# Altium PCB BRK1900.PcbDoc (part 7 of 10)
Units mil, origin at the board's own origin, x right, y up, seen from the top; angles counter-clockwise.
Board outline 8858.27 x 5905.51 mil, 10 copper layers (L1-TOP, L2-GND, L3-SIG1, L4-GND, L5-PWR, L6-PWR, L7-GND, L8-SIG2, L9-GND, L10-BOT), stack 48.824 mil thick; 507 components, 607 nets, 2498 pads, 2210 vias.
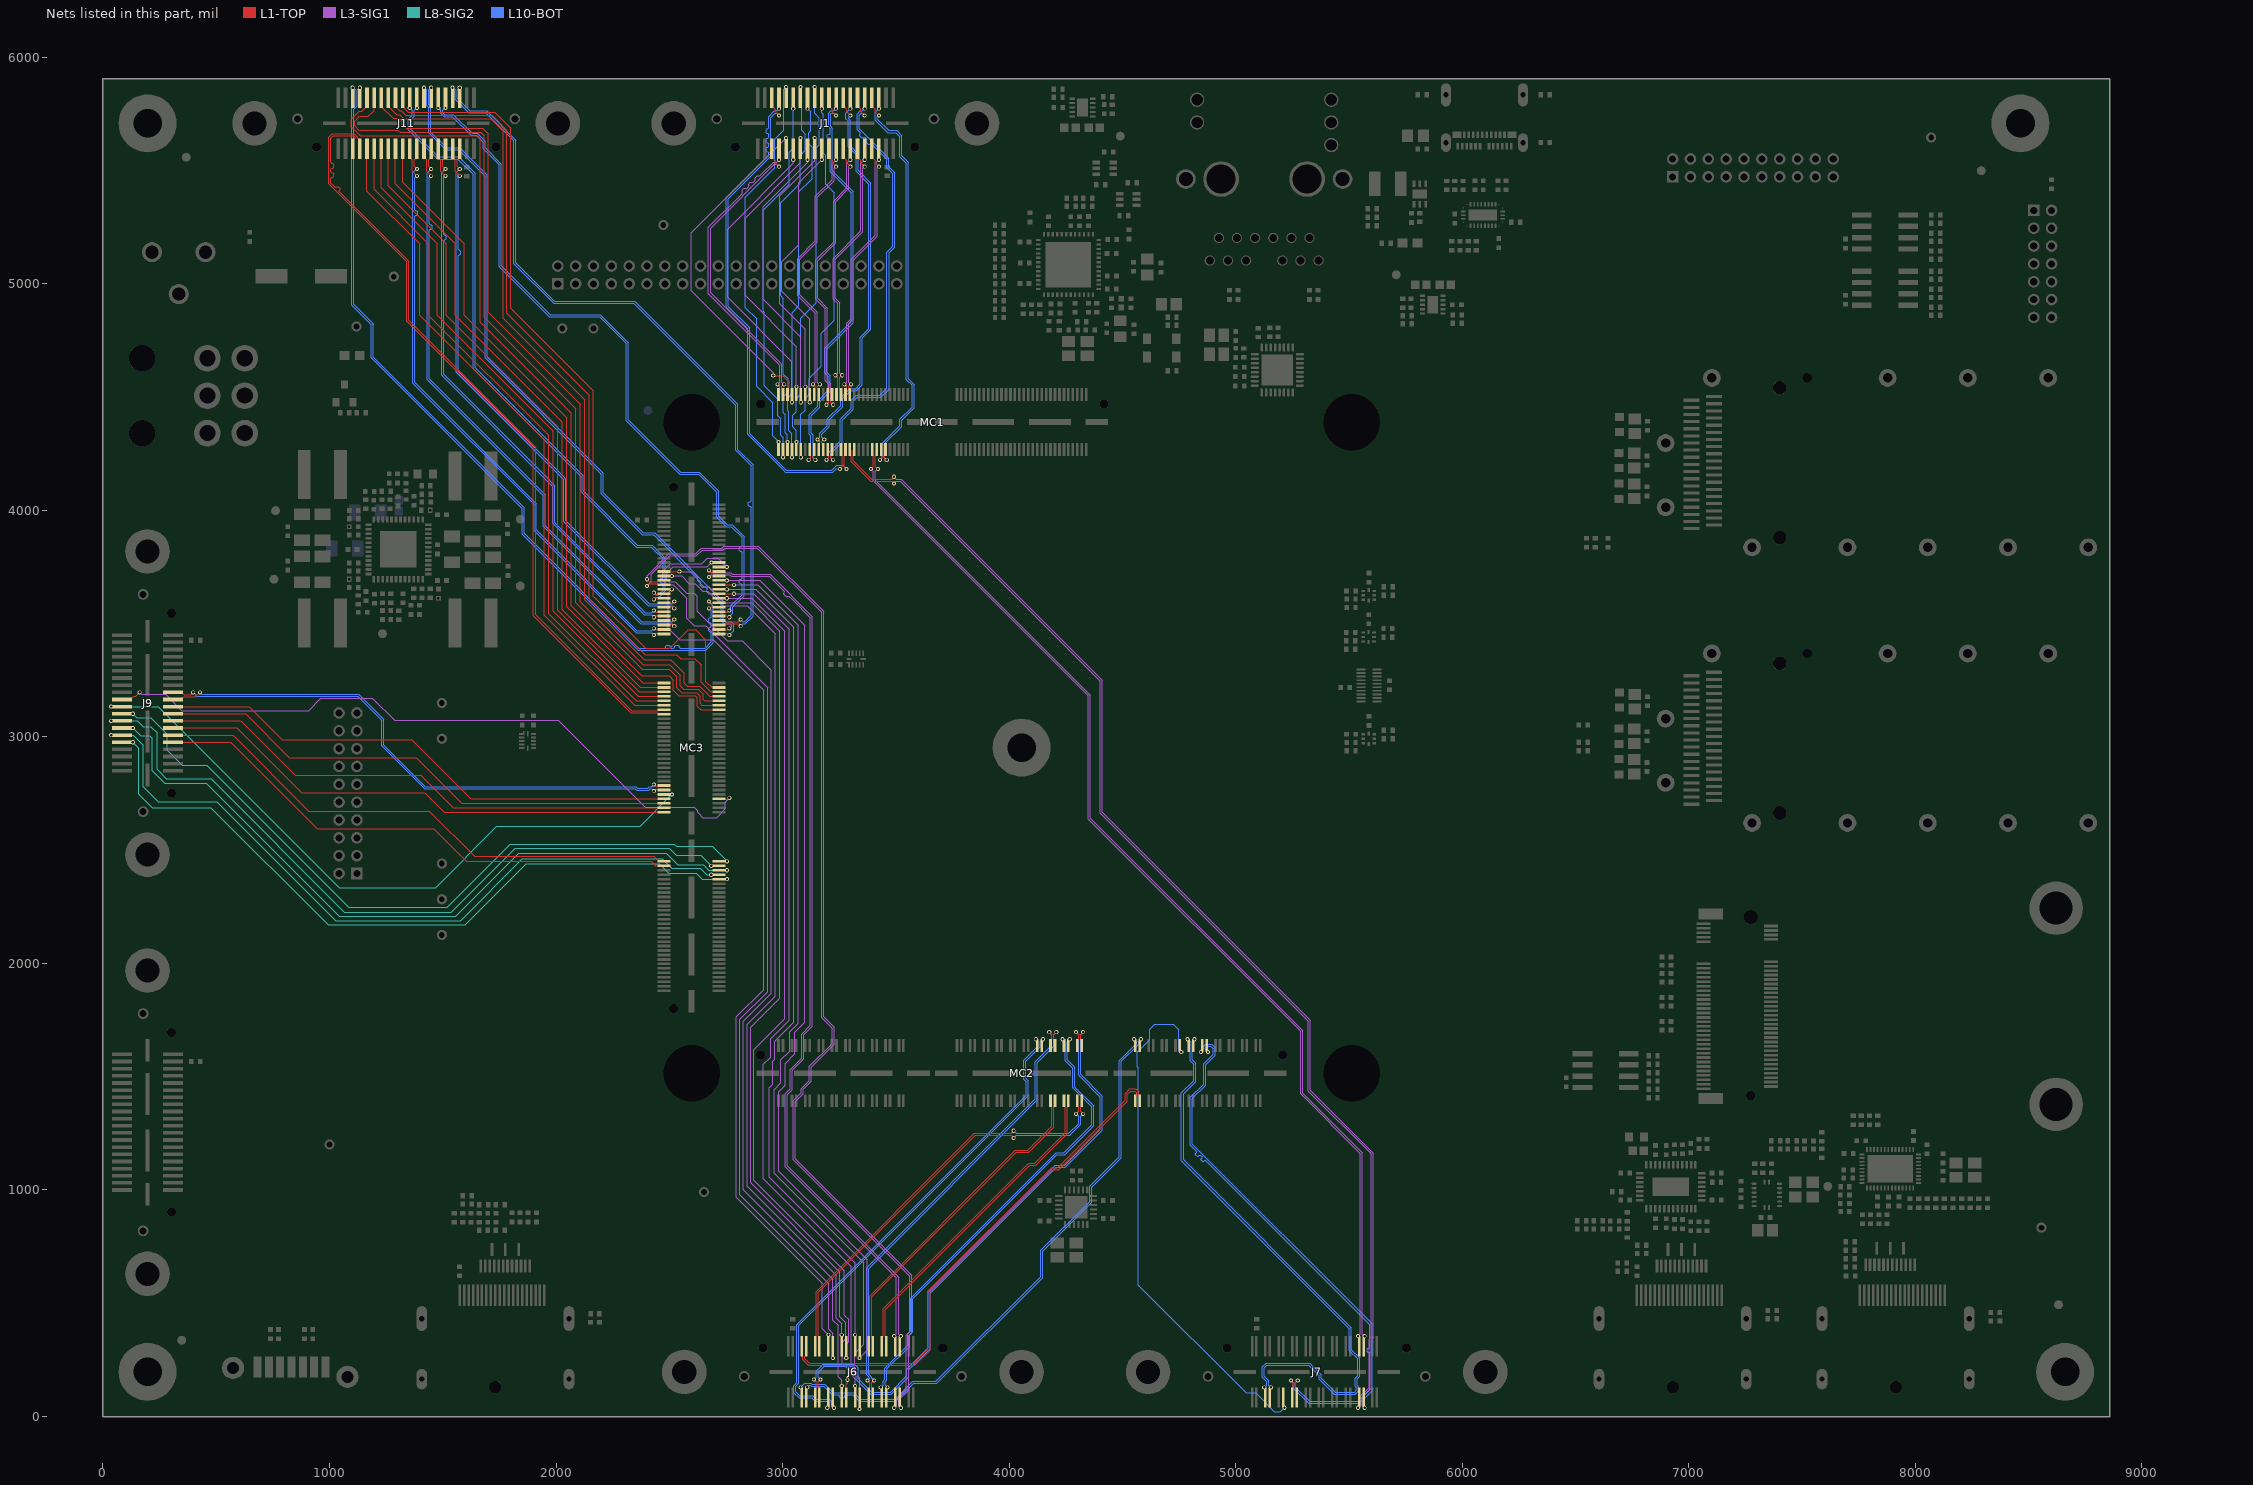
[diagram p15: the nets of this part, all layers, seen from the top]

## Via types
v1: diameter 18, hole 10, L1-TOP to L10-BOT, tented both sides, 2210 vias

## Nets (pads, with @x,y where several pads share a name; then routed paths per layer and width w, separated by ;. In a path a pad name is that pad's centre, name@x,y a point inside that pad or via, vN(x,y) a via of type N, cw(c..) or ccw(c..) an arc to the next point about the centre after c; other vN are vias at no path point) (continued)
SZG_PORTB_S13_D7P: J9.18 MC3.71 | length 2432.9
  L1-TOP w3.3: J9.18@309.65,3196.91 346.64,3196.91 357.89,3185.66 386.98,3185.66 v1(398.23,3196.91)
  L1-TOP w5.25: v1@2431.77,2761.81 2434.07,2761.81 2440.35,2768.09 2474.43,2768.09 MC3.71@2476.77,2765.75
  L10-BOT w3.3: v1(398.23,3196.91) 415.14,3180 1125,3180 1231,3074 1231,2960 1419.91,2771.09 2348.27,2771.09 2355.36,2764 2408.91,2764 2416,2771.09 2422.49,2771.09 v1@2431.77,2761.81
  other v1: 2431.77,2760.71
SZG_PORTB_S14_D6N: J9.19 MC3.68 | length 3074.3
  L1-TOP w3.3: J9.19@84.05,3165.41 120.41,3165.41 135,3180 144.76,3180 v1@161.66,3196.9
  L1-TOP w5.25: MC3.68@2720.08,2726.38 2722.42,2724.04 2756.5,2724.04 2762.78,2730.32 v1@2765.08,2730.32
  L3-SIG1 w3.15: v1@161.66,3196.9 170.56,3188 276.73,3188 348.36,3116.36 907.36,3116.36 962,3171 1189.73,3171 1287.73,3073 2009.1,3073 2016.1,3066 2172.1,2910 2393.42,2688.68 2609.95,2688.68 2625,2673.63 2625,2667 2648,2644 2709,2644 2747,2682 2747,2712.24 v1@2765.08,2730.32
  other v1: 2765.08,2731.32 162.16,3196.9
SZG_PORTB_S15_D7N: J9.20 MC3.73 | length 2432.9
  L1-TOP w3.3: J9.20@309.65,3165.41 346.51,3165.41 357.76,3176.66 407.51,3176.66 v1@427.76,3196.9
  L1-TOP w5.25: v1@2431.77,2789.37 2434.07,2789.37 2440.35,2783.09 2474.43,2783.09 MC3.73@2476.77,2785.43
  L10-BOT w3.3: v1@427.76,3196.9 435.66,3189 1128.73,3189 1240,3077.73 1240,2963.73 1423.64,2780.09 2352,2780.09 2359.09,2773 2405.18,2773 2412.27,2780.09 2422.49,2780.09 v1@2431.77,2789.37
  other v1: 2431.77,2790.37 428.26,3196.9
SZG_PORTB_S16: J9.21 MC3.69 | length 2976.9
  L8-SIG2 w4.05: v1(36.05,3133.91) 244.09,3133.91 1043,2335 1468.86,2335 1739.36,2605.5 2371.21,2605.5 v1(2511.77,2746.06)
SZG_PORTB_S17: J9.22 MC3.67 | length 2335.9
  L1-TOP w4.55: J9.22@309.65,3133.91 645.09,3133.91 791,2988 1362.39,2988 1624.02,2726.38 MC3.67@2476.77,2726.38
SZG_PORTB_S18: J9.23 MC3.60 | length 3165.7
  L8-SIG2 w4.05: v1(132.05,3102.41) 149.46,3085 210,3085 283,3012 283,2941 350,2874 459,2874 1085,2248 1519.65,2248 1798.65,2527 2521,2527 2531,2517 2688.87,2517 v1(2755.08,2450.79)
SZG_PORTB_S19: J9.24 MC3.65 | length 2331
  L1-TOP w4.55: J9.24@309.65,3102.41 629.59,3102.41 823,2909 1382.34,2909 1584.65,2706.69 MC3.65@2476.77,2706.69
SZG_PORTB_S20: J9.25 MC3.58 | length 3241.1
  L8-SIG2 w4.05: v1(36.05,3070.91) 151.09,3070.91 177,3045 212,3045 239,3018 239,2857 280,2816 477,2816 1066,2227 1538.02,2227 1819.02,2508 2500,2508 2530,2478 2638.18,2478 v1(2685.08,2431.1)
SZG_PORTB_S21: J9.26 MC3.63 | length 2326.1
  L1-TOP w4.55: J9.26@309.65,3070.91 608.09,3070.91 849,2830 1402.28,2830 1545.28,2687.01 MC3.63@2476.77,2687.01
SZG_PORTB_S22: J9.27 MC3.56 | length 3197.2
  L8-SIG2 w4.05: v1(132.05,3039.41) 166.46,3005 206,3005 217,2994 217,2851 273,2795 457,2795 1044,2208 1558.39,2208 1836.39,2486 2487,2486 2537,2436 2649,2436 2673.58,2411.42 v1(2755.08,2411.42)
SZG_PORTB_S23: J9.28 MC3.61 | length 2321.2
  L1-TOP w4.55: J9.28@309.65,3039.41 591.59,3039.41 878,2753 1420.23,2753 1505.91,2667.32 MC3.61@2476.77,2667.32
SZG_PORTB_S24: J9.29 MC3.54 | length 3238.2
  L8-SIG2 w4.05: v1(36.05,3007.91) 134.09,3007.91 178,2964 178,2780 244,2714 503,2714 1028,2189 1578.76,2189 1851.76,2462 2468,2462 2510,2420 2637,2420 2665.27,2391.73 v1(2685.08,2391.73)
SZG_PORTB_S25: J9.30 MC3.59 | length 2397.9
  L1-TOP w4.55: J9.30@309.65,3007.91 574.09,3007.91 909,2673 1441.17,2673 1640.17,2474 2431.9,2474 2455.11,2450.79 MC3.59@2476.77,2450.79
SZG_PORTB_S26: J9.31 MC3.52 | length 3215.6
  L8-SIG2 w4.05: v1(132.05,2976.41) 158,2950.46 158,2748 218,2688 476,2688 994,2170 1599.13,2170 1869.13,2440 2456,2440 2498,2398 2619,2398 2644.95,2372.05 v1(2755.08,2372.05)
SZG_PORTB_S27: J9.32 MC3.57 | length 2393
  L1-TOP w4.55: J9.32@309.65,2976.41 563.59,2976.41 946,2594 1461.12,2594 1603.62,2451.5 2420.5,2451.5 2440.9,2431.1 MC3.57@2476.77,2431.1
SZG_PORTC_C2P_CLKN: J11.36 MC3.107 | length 3437.8
  L1-TOP w3.3: J11.36@1102.38,5595.86 1102.38,5632.38 1113.63,5643.63 1113.63,5646.73 1106.51,5653.85 1016.85,5653.85 1006,5643 1006,5540.85 1006,5535.7 1010.06,5531.64 1013.94,5531.64 1018,5527.58 1018,5515.4 1013.94,5511.34 1010.06,5511.34 1006,5507.28 1006,5495.1 1010.06,5491.04 1013.94,5491.04 1018,5486.98 1018,5474.8 1013.94,5470.74 1010.06,5470.74 1006,5466.68 1006,5444.73 1022.86,5427.86 1024.03,5426.7 1029.77,5426.7 1032.52,5429.44 1038.26,5429.44 1046.87,5420.83 1046.87,5415.09 1044.13,5412.34 1044.13,5406.6 1056.86,5393.86 1350,5100.73 1350,4838.73 1909.45,4279.28 1909.45,3538.55 2333.26,3114.74 2448.6,3114.74 2453.95,3120.08 MC3.107@2476.77,3120.08
SZG_PORTC_C2P_CLKP: J11.34 MC3.105 | length 3439.1
  L1-TOP w3.3: J11.34@1133.88,5595.86 1133.88,5632.65 1122.63,5643.9 1122.63,5650.45 1110.24,5662.85 1013.12,5662.85 997,5646.73 997,5441 1341,5097 1341,4835 1360,4816 1900.45,4275.55 1900.45,3534.82 1962,3473.27 2329.54,3105.74 2400.54,3105.74 2448.92,3105.74 2454.26,3100.39 MC3.105@2476.77,3100.39
SZG_PORTC_P2C_CLKN: J11.35 MC3.136 | length 3600.8
  L1-TOP w5.25: v1@2675.08,3596.46 2677.38,3596.46 2683.66,3590.18 2717.74,3590.18 MC3.136@2720.08,3592.52
  L10-BOT w3.3: v1@1103.37,5866.17 1113.63,5855.9 1113.63,5789 1099,5774.37 1099,4906.27 1185,4820.27 ; 1185,4821 1185,4820.27 ; v1@2675.08,3596.46 2694.78,3576.76 2694.78,3416.05 2661.73,3383 2362.27,3383 1851,3894.27 1851,4007 1185,4673 1185,4820.27
  other v1: 2675.08,3597.46 1102.37,5866.17
SZG_PORTC_P2C_CLKP: J11.33 MC3.134 | length 3596
  L1-TOP w5.25: v1@2675.08,3568.9 2677.38,3568.9 2683.66,3575.18 2717.74,3575.18 MC3.134@2720.08,3572.83
  L10-BOT w3.3: v1@1132.89,5866.17 1122.63,5855.9 1122.63,5785.27 1108,5770.64 1108,4910 1195.5,4822.5 ; 1194,4821 1194,4676.73 1860,4010.73 1860,3898 2366,3392 2459,3392 2480.03,3392 2484.09,3396.06 2484.09,3399.94 2488.15,3404 2500.33,3404 2504.39,3399.94 2504.39,3396.06 2508.45,3392 2520.63,3392 2524.69,3396.06 2524.69,3399.94 2528.75,3404 2540.93,3404 2544.99,3399.94 2544.99,3396.06 2549.05,3392 2571,3392 2658,3392 2685.78,3419.78 2685.78,3452 2685.78,3460.03 2681.72,3464.09 2677.84,3464.09 2673.78,3468.15 2673.78,3480.33 2677.84,3484.39 2681.72,3484.39 2685.78,3488.45 2685.78,3500.63 2681.72,3504.69 2677.84,3504.69 2673.78,3508.75 2673.78,3520.93 2677.84,3524.99 2681.72,3524.99 2685.78,3529.05 2685.78,3551 2685.78,3558.2 v1@2675.08,3568.9
  other v1: 2675.08,3567.8 1133.89,5866.17
SZG_PORTC_S0_D0P: J11.5 MC3.126 | length 3303
  L1-TOP w3.3: MC3.126@2720.08,3494.09 2742.67,3494.09 2748.01,3499.44 2805.8,3499.44 v1@2815.08,3490.16
  L10-BOT w3.3: v1@1573.89,5866.17 1563.63,5855.9 1563.63,5819.37 1619.11,5763.89 1694.11,5763.89 1823,5635 1823,5093 1993,4923 2311.73,4923 2346.73,4923 2802,4467.73 2802,4432.73 2802,4268.73 2870,4200.73 2870,3533.71 2835.73,3499.44 2824.36,3499.44 v1@2815.08,3490.16
  other v1: 2815.08,3489.06 1574.89,5866.17
SZG_PORTC_S1_D1P: J11.6 MC3.133 | length 2552.1
  L1-TOP w3.3: v1(1574.88,5507.28) 1563.63,5518.53 1563.63,5547.62 1574.88,5558.87 J11.6@1574.88,5595.86
  L1-TOP w5.25: MC3.133@2476.77,3572.83 2479.11,3575.18 2513.19,3575.18 2519.47,3568.9 v1@2521.77,3568.9
  L10-BOT w3.3: v1(1574.88,5507.28) 1559,5491.4 1559,4914 1559,4610.27 2035,4134.27 2035,3950.13 2406.95,3578.18 2416.09,3578.18 2512.49,3578.18 v1@2521.77,3568.9
  other v1: 2521.77,3567.8
SZG_PORTC_S2_D0N: J11.7 MC3.128 | length 3302.6
  L1-TOP w3.3: MC3.128@2720.08,3513.78 2742.76,3513.78 2748.1,3508.44 2805.8,3508.44 v1@2815.08,3517.72
  L10-BOT w3.3: v1@1544.37,5866.17 1554.63,5855.9 1554.63,5815.64 1603.64,5766.64 1606.27,5764 1615.38,5754.89 1690.38,5754.89 1814,5631.27 1814,5089.27 1989.27,4914 2343,4914 2793,4464 2793,4265 2861,4197 2861,4065 2861,4043.05 2856.94,4038.99 2853.06,4038.99 2849,4034.93 2849,4022.75 2853.06,4018.69 2856.94,4018.69 2861,4014.63 2861,3995 2861,3537.44 2832,3508.44 2824.36,3508.44 v1@2815.08,3517.72
  other v1: 2815.08,3518.72 1543.37,5866.17
SZG_PORTC_S3_D1N: J11.8 MC3.135 | length 2551.6
  L1-TOP w3.3: J11.8@1543.38,5595.86 1543.38,5559 1554.63,5547.75 1554.63,5498 v1@1574.88,5477.75
  L1-TOP w5.25: MC3.135@2476.77,3592.52 2479.11,3590.18 2513.19,3590.18 2519.47,3596.46 v1@2521.77,3596.46
  L10-BOT w3.3: v1@1574.88,5477.75 1568,5470.87 1568,5160 1568,5153.37 1572.06,5149.31 1575.94,5149.31 1580,5145.25 1580,5133.07 1575.94,5129.01 1572.06,5129.01 1568,5124.95 1568,5103 1568,4614 2031,4151 2044,4138 2044,3953.86 2410.68,3587.18 2512.49,3587.18 v1@2521.77,3596.46
  other v1: 2521.77,3597.46 1574.88,5476.75
SZG_PORTC_S4_D2P: J11.9 MC3.130 | length 3104
  L1-TOP w5.25: MC3.130@2720.08,3533.46 2722.42,3535.81 2756.5,3535.81 2762.78,3529.53 v1@2765.08,3529.53
  L10-BOT w3.3: v1@1510.89,5776.76 1500.63,5766.5 1500.63,5756 1509.63,5747 1546.73,5747 1629.73,5664 1651.73,5664 1687,5628.73 1687,5600 1758,5529 1758,5080 1974,4864 2195.73,4864 2319,4740.73 2319,4400 2550,4169 2633,4169 2718.36,4083.64 2718.36,3973.64 2755,3937 2777.73,3937 2830,3884.73 2830,3624.27 2781,3575.27 2781,3545.45 v1@2765.08,3529.53
  other v1: 2765.08,3528.43 1511.89,5776.76
SZG_PORTC_S5_D3P: J11.10 MC3.129 | length 2538.5
  L1-TOP w3.3: v1(1511.88,5507.28) 1500.63,5518.53 1500.63,5547.62 1511.88,5558.87 J11.10@1511.88,5595.86
  L1-TOP w5.25: v1@2431.77,3529.53 2434.07,3529.53 2440.35,3535.81 2474.43,3535.81 MC3.129@2476.77,3533.46
  L10-BOT w3.3: v1(1511.88,5507.28) 1495,5490.4 1495,4872 1495,4596.27 1986,4105.27 1986,3942.38 2389.58,3538.81 2393.15,3538.81 2422.49,3538.81 v1@2431.77,3529.53
  other v1: 2431.77,3528.43
SZG_PORTC_S6_D2N: J11.11 MC3.132 | length 3101.7
  L1-TOP w5.25: MC3.132@2720.08,3553.15 2722.42,3550.81 2756.5,3550.81 2762.78,3557.09 v1@2765.08,3557.09
  L10-BOT w3.3: v1@1481.37,5776.76 1491.63,5766.5 1491.63,5752.27 1505.9,5738 1543,5738 1626,5655 1648,5655 1678,5625 1678,5596.27 1749,5525.27 1749,5076.27 1970.27,4855 2192,4855 2310,4737 2310,4432 2310,4402.27 2310,4396.27 2546.27,4160 2552.27,4160 2582,4160 2629.27,4160 2709.36,4079.91 2709.36,3969.91 2751.27,3928 2774,3928 2821,3881 2821,3866 2821,3844.05 2816.94,3839.99 2813.06,3839.99 2809,3835.93 2809,3823.75 2813.06,3819.69 2816.94,3819.69 2821,3815.63 2821,3809 2821,3713 2821,3700.07 2816.94,3696.01 2813.06,3696.01 2809,3691.95 2809,3679.77 2813.06,3675.71 2816.94,3675.71 2821,3671.65 2821,3670 2821,3628 2772,3579 2772,3564.01 v1@2765.08,3557.09
  other v1: 2765.08,3558.09 1480.37,5776.76
SZG_PORTC_S7_D3N: J11.12 MC3.131 | length 2538.1
  L1-TOP w3.3: J11.12@1480.38,5595.86 1480.38,5559 1491.63,5547.75 1491.63,5498 v1@1511.88,5477.75
  L1-TOP w5.25: v1@2431.77,3557.09 2434.07,3557.09 2440.35,3550.81 2474.43,3550.81 MC3.131@2476.77,3553.15
  L10-BOT w3.3: v1@1511.88,5477.75 1504,5469.87 1504,5233 1504,5218.37 1508.06,5214.31 1511.94,5214.31 1516,5210.25 1516,5198.07 1511.94,5194.01 1508.06,5194.01 1504,5189.95 1504,5168 1504,4600 1958,4146 1986,4118 1995,4109 1995,3946.11 2393.31,3547.81 2422.49,3547.81 v1@2431.77,3557.09
  other v1: 2431.77,3558.09 1511.88,5476.75
SZG_PORTC_S8_D4P: J11.13 MC3.122 | length 3112.3
  L1-TOP w5.25: MC3.122@2720.08,3454.72 2722.42,3457.07 2756.5,3457.07 2762.78,3450.79 v1@2765.08,3450.79
  L10-BOT w3.3: v1@1447.89,5866.17 1437.63,5855.9 1437.63,5791 1448,5780.63 1448,5670 1517,5601 1574.73,5601 1696,5479.73 1696,4676.73 2209,4163.73 2209,4150 2209,4077 2385,3901 2434.73,3901 2738,3597.73 2738,3517 2746,3509 2772.73,3509 2784,3497.73 2784,3469.71 v1@2765.08,3450.79
  other v1: 2765.08,3449.69 1448.89,5866.17
SZG_PORTC_S9_D5P: J11.14 MC3.125 | length 2703.3
  L1-TOP w3.3: v1(1448.88,5507.28) 1437.63,5518.53 1437.63,5547.62 1448.88,5558.87 J11.14@1448.88,5595.86
  L1-TOP w5.25: MC3.125@2476.77,3494.09 2479.11,3496.44 2513.19,3496.44 2519.47,3490.16 v1@2521.77,3490.16
  L10-BOT w3.3: v1(1448.88,5507.28) 1432,5490.4 1432,4903 1432,4844.27 1432,4576.27 1944,4064.27 1944,3929.16 2373.73,3499.44 2381.84,3499.44 2512.49,3499.44 v1@2521.77,3490.16
  other v1: 2521.77,3489.06
SZG_PORTC_S10_D4N: J11.15 MC3.124 | length 3110
  L1-TOP w5.25: MC3.124@2720.08,3474.41 2722.42,3472.07 2756.5,3472.07 2762.78,3478.35 v1@2765.08,3478.35
  L10-BOT w3.3: v1@1418.37,5866.17 1428.63,5855.9 1428.63,5787.27 1439,5776.9 1439,5666.27 1513.27,5592 1571,5592 1687,5476 1687,4954.27 1687,4673 2200,4160 2200,4082.27 2200,4073.27 2381.27,3892 2390.27,3892 2431,3892 2624,3699 2639.52,3683.48 2639.52,3677.74 2636.78,3674.99 2636.78,3669.25 2645.39,3660.64 2651.13,3660.64 2653.88,3663.38 2659.62,3663.38 2668.23,3654.77 2668.23,3649.03 2665.49,3646.28 2665.49,3640.54 2674.1,3631.93 2679.84,3631.93 2682.58,3634.67 2688.33,3634.67 2695.5,3627.5 2729,3594 2729,3513.27 2742.27,3500 2769,3500 2775,3494 2775,3488.27 v1@2765.08,3478.35
  other v1: 2765.08,3479.35 1417.37,5866.17
SZG_PORTC_S11_D5N: J11.16 MC3.127 | length 2702.8
  L1-TOP w3.3: J11.16@1417.38,5595.86 1417.38,5559 1428.63,5547.75 1428.63,5498 v1@1448.88,5477.75
  L1-TOP w5.25: MC3.127@2476.77,3513.78 2479.11,3511.44 2513.19,3511.44 2519.47,3517.72 v1@2521.77,3517.72
  L10-BOT w3.3: v1@1448.88,5477.75 1441,5469.87 1441,5283 1441,5264.37 1445.06,5260.31 1448.94,5260.31 1453,5256.25 1453,5244.07 1448.94,5240.01 1445.06,5240.01 1441,5235.95 1441,5214 1441,4580 1934,4087 1948,4073 1953,4068 1953,3932.89 2377.46,3508.44 2512.49,3508.44 v1@2521.77,3517.72
  other v1: 2521.77,3518.72 1448.88,5476.75
SZG_PORTC_S12_D6P: J11.17 MC3.137 | length 2814.6
  L1-TOP w5.25: v1@2431.77,3608.27 2434.07,3608.27 2440.35,3614.55 2474.43,3614.55 MC3.137@2476.77,3612.2
  L10-BOT w3.3: v1@1384.89,5776.76 1374.63,5766.5 1374.63,5740.27 1357,5722.64 1357,5684 1481,5560 1570.73,5560 1643,5487.73 1643,4630 2120,4153 2120,4085.73 2358.73,3847 2424.73,3847 2482,3789.73 2482,3644.82 2454.73,3617.55 2441.05,3617.55 v1@2431.77,3608.27
  other v1: 2431.77,3607.17 1385.89,5776.76
SZG_PORTC_S13_D7P: J11.18 MC3.121 | length 2691.6
  L1-TOP w3.3: v1(1385.88,5507.28) 1374.63,5518.53 1374.63,5547.62 1385.88,5558.87 J11.18@1385.88,5595.86
  L1-TOP w5.25: v1@2431.77,3450.79 2434.07,3450.79 2440.35,3457.07 2474.43,3457.07 MC3.121@2476.77,3454.72
  L10-BOT w3.3: v1(1385.88,5507.28) 1368,5489.4 1368,4928 1368,4802.27 1368,4561.27 1903,4026.27 1903,3926.34 1903,3910.3 2353.23,3460.07 2369.27,3460.07 2422.49,3460.07 v1@2431.77,3450.79
  other v1: 2431.77,3449.69
SZG_PORTC_S14_D6N: J11.19 MC3.139 | length 2814.2
  L1-TOP w5.25: v1@2431.77,3635.83 2434.07,3635.83 2440.35,3629.55 2474.43,3629.55 MC3.139@2476.77,3631.89
  L10-BOT w3.3: v1@1355.37,5776.76 1365.63,5766.5 1365.63,5744 1348,5726.37 1348,5680.27 1477.27,5551 1567,5551 1634,5484 1634,4917.27 1634,4626.27 2111,4149.27 2111,4082 2355,3838 2421,3838 2473,3786 2473,3712.04 2473,3705.07 2468.94,3701.01 2465.06,3701.01 2461,3696.95 2461,3684.77 2465.06,3680.71 2468.94,3680.71 2473,3676.65 2473,3675 2473,3648.55 2451,3626.55 2441.05,3626.55 v1@2431.77,3635.83
  other v1: 2431.77,3636.83 1354.37,5776.76
SZG_PORTC_S15_D7N: J11.20 MC3.123 | length 2691.8
  L1-TOP w3.3: J11.20@1354.38,5595.86 1354.38,5559 1365.63,5547.75 1365.63,5497.37 1385.88,5477.12 v1(1385.88,5476.75)
  L1-TOP w5.25: v1@2431.77,3478.35 2434.07,3478.35 2440.35,3472.07 2474.43,3472.07 MC3.123@2476.77,3474.41
  L10-BOT w3.3: v1@1385.88,5477.75 1377,5468.87 1377,5356 1377,5327.37 1381.06,5323.31 1384.75,5323.31 1388.81,5319.25 1388.81,5307.07 1384.75,5303.01 1381.06,5303.01 1377,5298.95 1377,5277 1377,4565 1912,4030 1912,3914.02 2356.96,3469.07 2422.49,3469.07 v1@2431.77,3478.35
  other v1: 2431.77,3479.35
SZG_PORTC_S16: J11.21 MC3.118 | length 3671.2
  L1-TOP w4.55: J11.21@1322.88,5821.46 1322.88,5781.9 1346.74,5758.04 1730.17,5758.04 1801.17,5687.04 1801.17,4891.74 2165.35,4527.56 2165.35,3620.65 2395,3391 2501,3391 2583,3473 2616.68,3473 2662,3427.67 2662,3244 2687.5,3218.5 MC3.118@2720.08,3218.5
SZG_PORTC_S17: J11.22 MC3.119 | length 2890.7
  L1-TOP w4.55: J11.22@1322.88,5595.86 1322.88,5448.77 1594.49,5177.17 1594.49,4862.2 2047.24,4409.45 2047.24,3573.76 2382.81,3238.19 MC3.119@2476.77,3238.19
SZG_PORTC_S18: J11.23 MC3.116 | length 3581.8
  L1-TOP w4.55: J11.23@1291.38,5821.46 1291.38,5782.78 1310.9,5763.26 1316.47,5763.26 1336.3,5743.43 1718.95,5743.43 1783.34,5679.04 1783.34,4870.21 2145.67,4507.87 2145.67,3610.33 2393.33,3362.67 2533.33,3362.67 2550,3346 2612,3346 2640,3318 2640,3242 2683.18,3198.82 MC3.116@2720.08,3198.82
SZG_PORTC_S19: J11.24 MC3.117 | length 2930
  L1-TOP w4.55: J11.24@1291.38,5595.86 1291.38,5440.9 1555.12,5177.17 1555.12,4862.2 2027.56,4389.76 2027.56,3562.44 2371.5,3218.5 MC3.117@2476.77,3218.5
SZG_PORTC_S20: J11.25 MC3.114 | length 3603.7
  L1-TOP w4.55: J11.25@1259.88,5821.46 1259.88,5783.31 1296.64,5746.56 1310.56,5746.56 1328.65,5728.47 1711.25,5728.47 1766.31,5673.41 1766.31,4847.86 2125.98,4488.19 2125.98,3605.02 2390,3341 2507,3341 2566,3282 2566,3238 2580,3224 2634,3224 2678.87,3179.13 MC3.114@2720.08,3179.13
SZG_PORTC_S21: J11.26 MC3.115 | length 2964.7
  L1-TOP w4.55: J11.26@1259.88,5595.86 1259.88,5433.03 1515.75,5177.17 1515.75,4862.2 2007.87,4370.08 2007.87,3559.13 2368.18,3198.82 MC3.115@2476.77,3198.82
SZG_PORTC_S22: J11.27 MC3.112 | length 3637
  L1-TOP w4.55: J11.27@1228.38,5821.46 1228.38,5782.8 1281.16,5730.03 1307.03,5730.03 1322.26,5714.8 1322.26,5702.85 1338.11,5687 1676,5687 1700.92,5662.08 1700.92,4873.89 2106.3,4468.5 2106.3,3596.7 2384,3319 2503,3319 2548.83,3273.17 2548.83,3226.8 2564.62,3211 2628,3211 2651,3188 2651,3165 2656.55,3159.45 MC3.112@2720.08,3159.45
SZG_PORTC_S23: J11.28 MC3.113 | length 3000
  L1-TOP w4.55: J11.28@1228.38,5595.86 1228.38,5425.16 1476.38,5177.17 1476.38,4862.2 1988.19,4350.39 1988.19,3554.81 2363.87,3179.13 MC3.113@2476.77,3179.13
SZG_PORTC_S24: J11.29 MC3.110 | length 3868.9
  L1-TOP w4.55: J11.29@1196.88,5821.46 1196.88,5765 1170.88,5739 1132,5739 1111,5718 1111,5698.08 1130.08,5679 1302.28,5679 1311.28,5670 1667,5670 1683,5654 1683,4852.43 2086.61,4448.82 2086.61,3591.39 2380,3298 2499,3298 2532.33,3264.67 2532.33,3217.18 2554.51,3195 2621,3195 2636,3180 2636,3148 2644.24,3139.76 MC3.110@2720.08,3139.76
SZG_PORTC_S25: J11.30 MC3.111 | length 3038.7
  L1-TOP w4.55: J11.30@1196.88,5595.86 1196.88,5417.29 1437.01,5177.17 1437.01,4862.2 1968.5,4330.71 1968.5,3544.5 2353.55,3159.45 MC3.111@2476.77,3159.45
SZG_PORTC_S26: J11.31 MC3.108 | length 3872.5
  L1-TOP w4.55: J11.31@1165.38,5821.46 1165.38,5784.71 1143.34,5762.66 1131.66,5762.66 1096,5727 1096,5694.07 1136.18,5653.88 1652.64,5653.88 1665.51,5641.01 1665.51,4830.55 2066.93,4429.13 2066.93,3580.07 2378,3269 2499,3269 2517,3251 2517,3206.6 2542.6,3181 2615,3181 2624,3172 2624,3136 2639.92,3120.08 MC3.108@2720.08,3120.08
SZG_PORTC_S27: J11.32 MC3.109 | length 3075.2
  L1-TOP w4.55: J11.32@1165.38,5595.86 1165.38,5409.42 1397.64,5177.17 1397.64,4862.2 1948.82,4311.02 1948.82,3538.18 2347.24,3139.76 MC3.109@2476.77,3139.76
SZG_PORTD_C2P_CLKN: J1.36 MC1.3 | length 1389.3
  L1-TOP w3.3: J1.36@2952.78,5595.86 2952.78,5559.51 2967.37,5544.91 2967.37,5535.15 v1@2984.27,5518.25 ; MC1.3@3001.97,4511.42 3001.97,4534.15 2996.63,4539.5 2996.63,4547.14 v1@3005.9,4556.42
  L3-SIG1 w3.15: v1@2984.27,5518.25 2974.01,5528.51 2964,5528.51 2682,5246.51 2682,4960 2996.63,4645.37 2996.63,4565.7 v1@3005.9,4556.42
  other v1: 3007,4556.42 2984.27,5517.25
SZG_PORTD_C2P_CLKP: J1.34 MC1.1 | length 1340.6
  L1-TOP w3.3: v1@2978.35,4556.42 2987.63,4547.14 2987.63,4539.49 2982.28,4534.15 MC1.1@2982.28,4511.42
  L3-SIG1 w3.15: v1@2978.35,4556.42 2987.63,4565.7 2987.63,4641.65 2673,4956.27 2673,5250.24 2821.38,5398.62 2822.49,5399.74 2822.49,5405.43 2821.12,5406.81 2821.12,5412.51 2829.67,5421.05 2835.37,5421.05 2836.74,5419.68 2842.44,5419.68 2850.99,5428.23 2850.99,5433.93 2849.88,5435.04 2849.88,5440.74 2858.43,5449.29 2864.12,5449.29 2865.24,5448.18 2870.94,5448.18 2879.49,5456.73 2879.49,5462.43 2879.48,5468.13 2888.03,5476.68 2893.73,5476.68 2899.43,5476.68 2910.38,5487.62 2960.27,5537.51 2974.01,5537.51 v1(2984.28,5547.78)
  other v1: 2977.25,4556.42
SZG_PORTD_P2C_CLKN: J1.35 MC1.32 | length 2251
  L1-TOP w3.3: J1.35@2952.78,5821.46 2952.78,5785.11 2967.37,5770.51 2967.37,5760.75 v1@2984.27,5743.85 ; MC1.32@3277.56,4268.11 3273.98,4264.53 3273.98,4241.56 3272.22,4239.8 3272.22,4192.39 v1@3281.5,4183.11
  L10-BOT w3.3: v1@2984.27,5743.85 2974.01,5754.11 2968,5754.11 2948,5734.11 2948,5563 2761,5376 2761,4899.73 2855,4805.73 2855,4339 3016.4,4177.6 3217.77,4177.6 3239.38,4199.2 3265.4,4199.2 v1@3281.5,4183.11
  other v1: 3282.6,4183.11 2984.27,5742.85
SZG_PORTD_P2C_CLKP: J1.33 MC1.30 | length 2195.4
  L1-TOP w3.3: v1@3253.94,4183.11 3263.22,4192.39 3263.22,4240.16 3257.87,4245.5 MC1.30@3257.87,4268.11
  L10-BOT w3.3: v1(2984.28,5773.38) 2974.01,5763.11 2964.27,5763.11 2939,5737.84 2939,5699 2939,5688.11 2934.94,5684.05 2931.06,5684.05 2927,5679.99 2927,5667.81 2931.06,5663.75 2934.94,5663.75 2939,5659.69 2939,5647.51 2934.94,5643.45 2931.06,5643.45 2927,5639.39 2927,5627.21 2931.06,5623.15 2934.94,5623.15 2939,5619.09 2939,5606.91 2934.94,5602.85 2931.06,5602.85 2927,5598.79 2927,5586.61 2931.06,5582.55 2934.94,5582.55 2939,5578.49 2939,5576.84 2939,5566.73 2752,5379.73 2752,4896 2846,4802 2846,4335.27 3002.27,4179 3010.27,4171 3012.67,4168.6 3221.5,4168.6 3223.9,4171 3236.01,4183.11 v1(3252.84,4183.11)
SZG_PORTD_S0_D0P: J1.5 MC1.48 | length 1754.6
  L1-TOP w3.3: v1@3431.1,4223.11 3440.38,4232.39 3440.38,4240.03 3435.04,4245.37 MC1.48@3435.04,4268.11
  L10-BOT w3.3: v1(3425.28,5773.38) 3409,5757.1 3409,5723.27 3464.27,5668 3500,5668 3518,5650 3518,5561.27 3546,5533.27 3546,4577.31 3571.64,4551.66 3571.64,4456.19 3517,4401.55 3517,4374 3440.38,4297.38 3440.38,4232.39 v1@3431.1,4223.11
  other v1: 3430,4223.11
SZG_PORTD_S1_D1P: J1.6 MC1.31 | length 1105.2
  L1-TOP w3.3: v1@3273.62,4556.42 3282.9,4547.14 3282.9,4539.49 3277.56,4534.15 MC1.31@3277.56,4511.42
  L3-SIG1 w3.15: v1@3273.62,4556.42 3282.9,4565.7 3282.9,4826.63 3303,4846.73 3303,5107.73 3410,5214.73 3410,5532.5 v1(3425.28,5547.78)
  other v1: 3272.52,4556.42
SZG_PORTD_S2_D0N: J1.7 MC1.50 | length 1812
  L1-TOP w3.3: J1.7@3393.78,5821.46 3393.78,5785.11 3408.37,5770.51 3408.37,5760.75 v1@3425.27,5743.85 ; MC1.50@3454.72,4268.11 3454.72,4245.38 3449.38,4240.04 3449.38,4232.39 v1@3458.66,4223.11
  L10-BOT w3.3: v1@3425.27,5743.85 3418,5736.58 3418,5727 3468,5677 3503.73,5677 3527,5653.73 3527,5565 3555,5537 3555,4581.03 3580.64,4555.39 3580.64,4452.46 3526,4397.82 3526,4370.27 3449.38,4293.65 3449.38,4232.39 v1@3458.66,4223.11
  other v1: 3459.76,4223.11 3425.27,5742.85
SZG_PORTD_S3_D1N: J1.8 MC1.33 | length 1162.6
  L1-TOP w3.3: MC1.33@3297.24,4511.42 3297.24,4534.15 3291.9,4539.5 3291.9,4547.14 v1@3301.18,4556.42 ; J1.8@3393.78,5595.86 3393.78,5559.51 3408.37,5544.91 3408.37,5535.15 v1@3425.27,5518.25
  L3-SIG1 w3.15: v1@3301.18,4556.42 3291.9,4565.7 3291.9,4822.9 3312,4843 3312,5104 3419,5211 3419,5511.98 v1@3425.27,5518.25
  other v1: 3302.28,4556.42 3425.27,5517.25
SZG_PORTD_S4_D2P: J1.9 MC1.24 | length 1894.4
  L1-TOP w3.3: v1@3194.88,4223.11 3204.16,4232.39 3204.16,4240.03 3198.82,4245.37 MC1.24@3198.82,4268.11
  L10-BOT w3.3: v1@3194.88,4223.11 3204.16,4232.39 3204.16,4253.73 3255,4304.57 3255,4401.73 3304,4450.73 3304,4487.01 3325.05,4508.06 3430.06,4508.06 3461,4539 3461,5140 3486,5165 3486,5486.27 3460,5512.27 3460,5550 3393.04,5616.96 3391.87,5618.13 3386.13,5618.13 3383.38,5615.39 3377.64,5615.39 3369.03,5624 3369.03,5629.74 3371.77,5632.49 3371.77,5638.23 3363.16,5646.84 3357.42,5646.84 3355.35,5644.77 3349.61,5644.77 3341,5653.39 3341,5659.13 3343.06,5661.19 3343.06,5666.94 3333.5,5676.5 3329,5681 3329,5748.84 3343.27,5763.11 3352.01,5763.11 v1(3362.28,5773.38)
  other v1: 3193.78,4223.11
SZG_PORTD_S5_D3P: J1.10 MC1.27 | length 1111.6
  L1-TOP w3.3: v1@3234.25,4596.42 3243.53,4587.14 3243.53,4539.73 3241.77,4537.97 3241.77,4515 MC1.27@3238.19,4511.42
  L3-SIG1 w3.15: v1@3234.25,4596.42 3243.53,4605.7 3243.53,4913.47 3224,4933 3224,5111.73 3346,5233.73 3346,5531.5 v1(3362.28,5547.78)
  other v1: 3233.15,4596.42
SZG_PORTD_S6_D2N: J1.11 MC1.26 | length 1943.1
  L1-TOP w3.3: MC1.26@3218.5,4268.11 3218.5,4245.38 3213.16,4240.04 3213.16,4232.39 v1@3222.44,4223.11 ; J1.11@3330.78,5821.46 3330.78,5785.11 3345.37,5770.51 3345.37,5760.75 v1@3362.27,5743.85
  L10-BOT w3.3: v1@3222.44,4223.11 3213.16,4232.39 3213.16,4250 3264,4300.84 3264,4398 3313,4447 3313,4483.28 3328.78,4499.06 3433.79,4499.06 3440.73,4506 3470,4535.27 3470,5136.27 3495,5161.27 3495,5490 3469,5516 3469,5553.73 3338,5684.73 3338,5745.11 3347,5754.11 3352.01,5754.11 v1@3362.27,5743.85
  other v1: 3223.54,4223.11 3362.27,5742.85
SZG_PORTD_S7_D3N: J1.12 MC1.29 | length 1169
  L1-TOP w3.3: MC1.29@3257.87,4511.42 3257.87,4534.02 3252.53,4539.37 3252.53,4587.14 v1@3261.81,4596.42 ; J1.12@3330.78,5595.86 3330.78,5559.51 3345.37,5544.91 3345.37,5535.15 v1@3362.27,5518.25
  L3-SIG1 w3.15: v1@3261.81,4596.42 3252.53,4605.7 3252.53,4917.2 3233,4936.73 3233,5108 3355,5230 3355,5510.98 v1@3362.27,5518.25
  other v1: 3262.91,4596.42 3362.27,5517.25
SZG_PORTD_S8_D4P: J1.13 MC1.20 | length 1669.6
  L1-TOP w3.3: v1@3155.51,4313.11 3164.79,4303.83 3164.79,4296.18 3159.45,4290.84 MC1.20@3159.45,4268.11
  L10-BOT w3.3: v1@3155.51,4313.11 3164.79,4322.39 3164.79,4340.73 3198,4373.94 3198,4403.71 3256,4461.71 3256,4497.73 3296.27,4538 3322,4538 3343,4559 3343,4764.73 3381,4802.73 3381,5440.73 3325,5496.73 3325,5569 3289,5605 3289,5719.27 3280,5728.27 3280,5754.1 v1(3299.28,5773.38)
  other v1: 3154.41,4313.11
SZG_PORTD_S9_D5P: J1.14 MC1.23 | length 1223.8
  L1-TOP w3.3: v1@3194.88,4466.42 3204.16,4475.7 3204.16,4483.34 3198.82,4488.68 MC1.23@3198.82,4511.42
  L3-SIG1 w3.15: v1@3194.88,4466.42 3204.16,4475.7 3204.16,4556 3189,4571.16 3189,4889 3146,4932 3146,5105.73 3225,5184.73 3225,5365.73 3284,5424.73 3284,5532.5 v1(3299.28,5547.78)
  other v1: 3193.78,4466.42
SZG_PORTD_S10_D4N: J1.15 MC1.22 | length 1725
  L1-TOP w3.3: MC1.22@3179.13,4268.11 3179.13,4290.85 3173.79,4296.19 3173.79,4303.83 v1@3183.07,4313.11 ; J1.15@3267.78,5821.46 3267.78,5785.11 3282.37,5770.51 3282.37,5760.75 v1@3299.27,5743.85
  L10-BOT w3.3: v1@3183.07,4313.11 3173.79,4322.39 3173.79,4337 3207,4370.21 3207,4399.98 3265,4457.98 3265,4464 3265,4494 3300,4529 3325.73,4529 3352,4555.27 3352,4761 3390,4799 3390,5444.46 3334,5500.46 3334,5572.73 3298,5608.73 3298,5723 3291.41,5729.59 3291.41,5735.99 v1@3299.27,5743.85
  other v1: 3184.17,4313.11 3299.27,5742.85
SZG_PORTD_S11_D5N: J1.16 MC1.25 | length 1281.2
  L1-TOP w3.3: MC1.25@3218.5,4511.42 3218.5,4488.69 3213.16,4483.34 3213.16,4475.7 v1@3222.44,4466.42 ; J1.16@3267.78,5595.86 3267.78,5559.51 3282.37,5544.91 3282.37,5535.15 v1@3299.27,5518.25
  L3-SIG1 w3.15: v1@3222.44,4466.42 3213.16,4475.7 3213.16,4559.73 3198,4574.89 3198,4892.73 3155,4935.73 3155,5102 3234,5181 3234,5362 3293,5421 3293,5511.98 v1@3299.27,5518.25
  other v1: 3223.54,4466.42 3299.27,5517.25
SZG_PORTD_S12_D6P: J1.17 MC1.16 | length 1779.3
  L1-TOP w3.3: v1@3116.14,4223.11 3125.42,4232.39 3125.42,4240.03 3120.08,4245.37 MC1.16@3120.08,4268.11
  L10-BOT w3.3: v1@3116.14,4223.11 3125.42,4232.39 3125.42,4329 3118,4336.42 3118,4421.73 3155,4458.73 3155,4482.73 3202,4529.73 3202,4591 3186,4607 3186,4714.73 3204,4732.73 3303,4831.73 3303,5402 3210.12,5494.88 3210.12,5640.68 3210.12,5642.33 3207.67,5644.78 3200.73,5644.78 3198.28,5647.22 3198.28,5658.63 3200.73,5661.08 3207.67,5661.08 3210.12,5663.52 3210.12,5668 3210.12,5684.15 3203,5691.27 3203,5753.84 3212.27,5763.11 3226.01,5763.11 v1(3236.28,5773.38)
  other v1: 3115.04,4223.11
SZG_PORTD_S13_D7P: J1.18 MC1.17 | length 1148.7
  L1-TOP w3.3: v1@3135.83,4556.42 3145.11,4547.14 3145.11,4539.49 3139.76,4534.15 MC1.17@3139.76,4511.42
  L3-SIG1 w3.15: v1@3135.83,4556.42 3145.11,4565.7 3145.11,4869.89 3067,4948 3067,5111.73 3145.11,5189.83 3145.11,5385.83 3219,5459.73 3219,5530.5 v1(3236.28,5547.78)
  other v1: 3134.73,4556.42
SZG_PORTD_S14_D6N: J1.19 MC1.18 | length 1837.5
  L1-TOP w3.3: MC1.18@3139.76,4268.11 3139.76,4245.38 3134.42,4240.04 3134.42,4232.39 v1@3143.7,4223.11 ; J1.19@3204.78,5821.46 3204.78,5785.11 3219.37,5770.51 3219.37,5760.75 v1@3236.27,5743.85
  L10-BOT w3.3: v1@3143.7,4223.11 3134.42,4232.39 3134.42,4332.73 3127,4340.15 3127,4418 3164,4455 3164,4479 3211,4526 3211,4594.73 3195,4610.73 3195,4711 3312,4828 3312,5405.73 3219.12,5498.61 3219.12,5679.39 3219.64,5679.91 3219.64,5687.36 3217,5690 3212,5695 3212,5750.11 3216,5754.11 3226.01,5754.11 v1@3236.27,5743.85
  other v1: 3144.8,4223.11 3236.27,5742.85
SZG_PORTD_S15_D7N: J1.20 MC1.19 | length 1206.1
  L1-TOP w3.3: MC1.19@3159.45,4511.42 3159.45,4534.15 3154.11,4539.5 3154.11,4547.14 v1@3163.39,4556.42 ; J1.20@3204.78,5595.86 3204.78,5559.51 3219.37,5544.91 3219.37,5535.15 v1@3236.27,5518.25
  L3-SIG1 w3.15: v1@3163.39,4556.42 3154.11,4565.7 3154.11,4873.62 3076,4951.73 3076,5108 3154.11,5186.11 3154.11,5382.11 3228,5456 3228,5509.98 v1@3236.27,5518.25
  other v1: 3164.49,4556.42 3236.27,5517.25
SZG_PORTD_S16: J1.21 MC1.12 | length 1623
  L10-BOT w4.55: v1(3080.71,4234.11) 3080.71,4423.71 3100,4443 3100,4495 3118,4513 3118,4584 3171,4637 3171,4783 3228,4840 3228,5402 3191.03,5438.97 3191.03,5566.78 3180.5,5577.32 3180.5,5748.5 3173.28,5755.72 v1(3173.28,5773.46)
SZG_PORTD_S17: J1.22 MC1.15 | length 1196.2
  L3-SIG1 w4.05: v1(3120.08,4477.42) 3120.08,4537 3118,4539.08 3118,4568.92 3120.08,4571 3120.08,4843.92 2997,4967 2997,5097 3072,5172 3072,5446.59 v1(3173.28,5547.86)
SZG_PORTD_S18: J1.23 MC1.10 | length 1632.5
  L10-BOT w4.55: v1(3061.02,4302.11) 3061.02,4352.04 3044,4369.07 3044,4419 3061,4436 3061,4492 3081,4512 3081,4849 3149,4917 3149,5601 3163,5615 3163,5731 3141.78,5752.22 v1(3141.78,5869.46)
SZG_PORTD_S19: J1.24 MC1.13 | length 1208.9
  L3-SIG1 w4.05: v1(3100.39,4545.42) 3100.39,4800.61 2987.81,4913.19 2987.81,5388.81 3141.78,5542.78 v1(3141.78,5643.86)
SZG_PORTD_S20: J1.25 MC1.8 | length 1607.7
  L10-BOT w4.55: v1(3041.34,4234.11) 3041.34,4337.66 3028,4351 3028,4434 3022,4440 3022,4496 3042,4516 3042,4873 3072,4903 3072,5407 3130,5465 3130,5603 3115,5618 3115,5666 3124,5675 3124,5759.74 v1(3110.28,5773.46)
SZG_PORTD_S21: J1.26 MC1.11 | length 1220.8
  L3-SIG1 w4.05: v1(3080.71,4477.42) 3080.71,4764.29 2914,4931 2914,5339.8 3110.28,5536.07 v1(3110.28,5547.86)
SZG_PORTD_S22: J1.27 MC1.6 | length 1652.2
  L10-BOT w4.55: v1(3021.65,4302.11) 3021.65,4333.35 3011.47,4343.53 3011.47,4424.53 3004,4432 3004,4502 3026,4524 3026,4580 3004,4602 3004,4935 2992,4947 2992,5358 3077,5443 3077,5565 3101,5589 3101,5661 3084,5678 3084,5805 3078.78,5810.22 v1(3078.78,5869.46)
SZG_PORTD_S23: J1.28 MC1.9 | length 1293
  L3-SIG1 w4.05: v1(3061.02,4545.42) 3061.02,4722.98 2835,4949 2835,5290.17 3078.78,5533.95 v1(3078.78,5643.86)
SZG_PORTD_S24: J1.29 MC1.4 | length 1631
  L10-BOT w4.55: v1(3001.97,4234.11) 3001.97,4321.03 2992,4331 2992,4404 2978,4418 2978,4491 2919,4550 2919,4874 2914,4879 2914,5325 3029.72,5440.72 3029.72,5581.72 3047.28,5599.28 v1(3047.28,5773.46)
SZG_PORTD_S25: J1.30 MC1.7 | length 1308.5
  L3-SIG1 w4.05: v1(3041.34,4477.42) 3041.34,4656.66 2757,4941 2757,5241.83 3047.28,5532.11 v1(3047.28,5547.86)
SZG_PORTD_S26: J1.31 MC1.2 | length 1703.2
  L10-BOT w4.55: v1(2982.28,4302.11) 2956,4328.39 2956,4476 2885,4547 2885,4845 2835,4895 2835,5382 2965,5512 2965,5639 3005,5679 3005,5858.69 v1(3015.78,5869.46)
SZG_PORTD_S27: J1.32 MC1.5 | length 1513.3
  L1-TOP w4.55: v1(2959,4595) 3001,4595 3030,4566 3030,4545 3021.65,4536.65 MC1.5@3021.65,4511.42
  L3-SIG1 w4.05: v1(2959,4595) 2959,4608.07 2597,4970.07 2597,5225.09 v1(3015.78,5643.86)
SZG_PORTE_C2P_CLKN: J6.36 MC3.150 | length 4018.9
  L1-TOP w5.25: v1@2675.08,3734.25 2677.38,3734.25 2683.66,3727.97 2717.74,3727.97 MC3.150@2720.08,3730.32
  L3-SIG1 w3.15: v1@2675.08,3734.25 2684.36,3724.97 2770.76,3724.97 2777.99,3717.74 2925.99,3717.74 2944.99,3717.74 3132,3530.73 3132,3511.73 3132,1727.27 3132,1722.63 3093.64,1684.26 3093.64,1578.64 3043,1528 3043,1443 3020.95,1420.95 3020.95,1106.78 3511.93,615.8 3511.93,364.12 v1@3521.21,354.84
  other v1: 3522.31,354.84 2675.08,3735.25
SZG_PORTE_C2P_CLKP: J6.34 MC3.148 | length 4018.7
  L1-TOP w5.25: v1@2675.08,3706.69 2677.38,3706.69 2683.66,3712.97 2717.74,3712.97 MC3.148@2720.08,3710.63
  L3-SIG1 w3.15: v1@2675.08,3706.69 2684.36,3715.97 2767.03,3715.97 2774.26,3708.74 2941.26,3708.74 2991,3659 3007.78,3642.22 3007.78,3637.52 3004.51,3634.26 3004.51,3629.56 3015.47,3618.59 3020.17,3618.59 3023.44,3621.86 3028.14,3621.86 3043,3607 3123,3527 3123,1726.35 3084.64,1687.99 3084.64,1582.36 3034,1531.73 3034,1446.73 3011.95,1424.68 3011.95,1103.05 3502.93,612.07 3502.93,364.12 v1@3493.65,354.84
  other v1: 3492.55,354.84 2675.08,3705.59
SZG_PORTE_P2C_CLKN: J6.35 MC3.145 | length 4896
  L1-TOP w3.3: v1@2401.77,3694.88 2411.05,3685.6 2448.88,3685.6 2454.22,3690.95 MC3.145@2476.77,3690.95
  L3-SIG1 w3.15: v1(2401.77,3695.88) 2401.77,3712.5 2497.21,3807.94 2616.21,3807.94 2639.77,3831.5 2641.27,3833 2732.27,3833 2741.27,3842 2892.73,3842 3181,3553.73 3181,1764.31 3227.84,1717.47 3227.84,1642.84 3127,1542 3127,1479.27 3091.64,1443.91 3091.64,1424.64 3089,1422 3056.24,1389.24 3056.24,1137.49 3570,623.73 3570,374 3570,369.93 3556,355.93 3556,117.07 3511.93,73 3511.93,48.14 v1@3521.21,38.86
  other v1: 3522.31,38.86
SZG_PORTE_P2C_CLKP: J6.33 MC3.143 | length 4898.5
  L1-TOP w3.3: v1@2401.77,3667.32 2411.05,3676.6 2448.69,3676.6 2454.03,3671.26 MC3.143@2476.77,3671.26
  L3-SIG1 w3.15: v1@2401.77,3667.32 2419.54,3685.09 2419.54,3717.54 2500.94,3798.94 2619.94,3798.94 2622,3801 2645,3824 2736,3824 2745,3833 2889,3833 3172,3550 3172,1760.58 3218.84,1713.74 3218.84,1646.57 3118,1545.73 3118,1483 3082.64,1447.64 3082.64,1428.36 3047.24,1392.97 3047.24,1133.76 3561,620 3561,373.66 3547,359.66 3547,120.8 3502.93,76.73 3502.93,48.14 v1@3493.65,38.86
  other v1: 3492.55,38.86 2401.77,3666.22
SZG_PORTE_REFCLKN: J6.15 MC2.67 | length 2224.1
  L10-BOT w3.3: v1@3225.93,38.86 3216.65,48.14 3216.65,65.73 3206.38,76 3148,76 3132.36,91.64 3076.36,91.64 3059,109 3059,133 3072,146 3072,402 4085,1415 4085,1481.73 4073.36,1493.36 4073.36,1568 4138.36,1632.99 4138.36,1654.15 v1(4149.61,1665.4)
  other v1: 3227.03,38.86
SZG_PORTE_REFCLKP: J6.13 MC2.65 | length 2224.1
  L10-BOT w3.3: v1@3198.38,38.86 3207.65,48.14 3207.65,62 3202.65,67 3144.27,67 3128.64,82.64 3072.64,82.64 3050,105.27 3050,136.73 3063,149.73 3063,405.73 4076,1418.73 4076,1478 4067,1487 4064.36,1489.64 4064.36,1571.73 4129.36,1636.72 4129.36,1654.15 v1(4118.11,1665.4)
  other v1: 3197.28,38.86
SZG_PORTE_RX0N: J6.7 MC2.83 | length 2547.6
  L10-BOT w3.3: v1@3107.82,128.86 3115.97,137 3122,137 3125.91,133.09 3181.91,133.09 3219,96 3224,96 3247.95,96 3251.3,92.66 3251.3,86.69 3254.64,83.34 3270.25,83.34 3273.6,86.69 3273.6,92.66 3276.94,96 3300,96 3310.27,96 3338.27,68 3500.76,68 3578.76,146 3680.73,146 4148,613.27 4148,729.27 4364,945.27 4364,1012.19 4495,1143.19 4495,1146 4495,1567.69 4571.43,1644.12 4571.43,1654.15 v1(4582.68,1665.4)
  other v1: 3108.92,128.86
SZG_PORTE_RX0P: J6.5 MC2.81 | length 2546.5
  L10-BOT w3.3: v1@3080.27,128.86 3097.41,146 3125.73,146 3129.64,142.09 3185.64,142.09 3222.73,105 3314,105 3342,77 3497.03,77 3575.03,155 3677,155 4139,617 4139,733 4355,949 4355,1015.92 4486,1146.92 4486,1571.42 4562.43,1647.85 4562.43,1654.15 v1(4551.18,1665.4)
  other v1: 3079.17,128.86
SZG_PORTE_RX1N: J6.11 MC2.79 | length 2652.1
  L1-TOP w3.3: J6.11@3162.94,83.86 3159.52,87.28 3159.52,126.15 3157.6,128.07 3157.6,154.58 v1@3166.88,163.86 ; MC2.79@4320.87,1637.4 4320.87,1660.3 4315.52,1665.65 4315.52,1685.65 v1(4326.77,1696.9)
  L10-BOT w3.3: v1@3166.88,163.86 3157.6,173.14 3157.6,196 3183.6,222 3313,222 3326,209 3326,163 3389.87,99.13 3480.74,99.13 3558,176.39 3558,206 3652,300 3652,545 4208,1101 4248.73,1101 4412,1264.27 4412,1414 4315.52,1510.48 4315.52,1685.65 v1(4326.77,1696.9)
  other v1: 3167.98,163.86
SZG_PORTE_RX1P: J6.9 MC2.77 | length 2652.1
  L1-TOP w3.3: v1@3139.32,163.86 3148.6,154.58 3148.6,128.74 3143.26,123.4 J6.9@3143.26,83.86 ; v1(4295.28,1696.9) 4306.52,1685.65 4306.52,1665.63 4301.18,1660.29 MC2.77@4301.18,1637.4
  L10-BOT w3.3: v1@3139.32,163.86 3148.6,173.14 3148.6,199.73 3179.87,231 3316.73,231 3335,212.73 3335,166.73 3393.6,108.13 3477.01,108.13 3549,180.12 3549,209.73 3643,303.73 3643,548.73 4204.27,1110 4245,1110 4403,1268 4403,1410.27 4306.52,1506.75 4306.52,1685.65 v1(4295.28,1696.9)
  other v1: 3138.22,163.86
SZG_PORTE_RX2N: J6.31 MC2.75 | length 1994.2
  L10-BOT w3.3: v1@3462.15,128.86 3452.88,138.14 3452.88,153 3460,160.12 3460,210 3552,302 3561,311 3561,361 3574,374 3574,519 4211,1156 4244.73,1156 4373,1284.27 4373,1371 4290,1454 4290,1541 4256.47,1574.53 4256.47,1654.15 v1(4267.72,1665.4)
  other v1: 3463.26,128.86
SZG_PORTE_RX2P: J6.29 MC2.73 | length 1994.2
  L10-BOT w3.3: v1@3434.6,128.86 3443.88,138.14 3443.88,156.73 3451,163.85 3451,213.73 3552,314.73 3552,364.73 3565,377.73 3565,522.73 4207.27,1165 4241,1165 4364,1288 4364,1367.27 4281,1450.27 4281,1537.27 4247.47,1570.8 4247.47,1654.15 v1(4236.22,1665.4)
  other v1: 3433.5,128.86
SZG_PORTE_RX3N: J6.27 MC2.71 | length 2038.3
  L1-TOP w3.3: J6.27@3399.16,83.86 3399.16,123.22 3393.82,128.57 3393.82,149.58 v1@3403.1,158.86 ; MC2.71@4202.76,1637.4 4202.76,1660.19 4197.41,1665.53 4197.41,1685.65 v1(4208.66,1696.9)
  L10-BOT w3.3: v1@3403.1,158.86 3393.82,168.14 3393.82,173.73 3380,187.55 3380,653.27 4125,1398.27 4125,1562.27 4197.41,1634.69 4197.41,1685.65 v1(4208.66,1696.9)
  other v1: 3404.2,158.86
SZG_PORTE_RX3P: J6.25 MC2.69 | length 2038.3
  L1-TOP w3.3: v1@3375.54,158.86 3384.82,149.58 3384.82,128.43 3379.48,123.09 J6.25@3379.48,83.86 ; v1(4177.17,1696.9) 4188.41,1685.65 4188.41,1665.11 4183.07,1659.76 MC2.69@4183.07,1637.4
  L10-BOT w3.3: v1@3375.54,158.86 3384.82,168.14 3384.82,170 3371,183.82 3371,657 4116,1402 4116,1566 4188.41,1638.41 4188.41,1685.65 v1(4177.17,1696.9)
  other v1: 3374.44,158.86
SZG_PORTE_S0: J6.14 MC3.141 | length 3776.6
  L3-SIG1 w4.05: v1(2510.77,3651.58) 2495,3635.8 2495,3480 2547,3428 2694,3428 2917,3205 2917,1885 2796,1764 2796,968 3175,589 3175,388.15 v1(3202.31,360.84)
SZG_PORTE_S1: J6.16 MC3.152 | length 4252.9
  L3-SIG1 w4.05: v1(2754.08,3750) 2715.08,3789 2668,3789 2643,3764 2504,3764 2471,3731 2471,3692 2491.74,3671.26 2516.74,3671.26 2576,3612 2576,3524 2610,3490 2661,3490 2935,3216 2935,1876 2812,1753 2812,979 3204,587 3204,386 3222,368 v1(3222,258.84)
SZG_PORTE_S2: J6.17 MC3.154 | length 4302.9
  L3-SIG1 w4.05: v1(2686.08,3769.69) 2667.39,3751 2518,3751 2486,3719 2486,3699 2500,3685 2526,3685 2576,3635 2610,3635 2624,3621 2624,3555 2755,3424 2821,3424 2951,3294 2951,1868 2827,1744 2827,1002 3222,607 3222,425 3244.74,402.27 3244.74,176.26 3261.37,159.63 v1(3261.37,134.86)
SZG_PORTE_S3: J6.18 MC3.147 | length 3880.7
  L3-SIG1 w4.05: v1(2510.77,3710.63) 2555.37,3710.63 2589,3677 2614,3677 2648,3643 2670,3643 2735,3578 2845,3578 2967,3456 2967,1855 2844,1732 2844,1016 3236,624 3236,434 3261.37,408.63 v1(3261.37,360.84)
SZG_PORTE_S4: J6.19 MC3.149 | length 4260.2
  L1-TOP w4.55: MC3.149@2476.77,3730.32 2477.07,3730.01 v1(2544.27,3730.01) ; J6.19@3281.05,83.86 3281,83.91 3281,144 3287.11,150.11 v1(3287.11,162.52)
  L3-SIG1 w4.05: v1(2544.27,3730.01) 2600.99,3730.01 2626,3705 2626,3689 2652.5,3662.5 2674.5,3662.5 2745,3592 2863,3592 2988,3467 2988,1847 2859,1718 2859,1032 3253,638 3253,441 3280,414 3280,344 3263,327 3263,235 3287.11,210.89 v1(3287.11,162.52)
SZG_PORTE_S5: J6.20 MC3.138 | length 3758.5
  L3-SIG1 w4.05: v1(2754.08,3612.2) 2864.8,3612.2 3010,3467 3010,2669 3010,1756 2873,1619 2873,1044 3273,644 3273,447 3291.36,428.64 3291.36,330.36 3281.05,320.05 v1(3281.05,258.84)
SZG_PORTE_S6: J6.21 MC3.140 | length 3928.8
  L1-TOP w4.55: MC3.140@2720.08,3631.89 v1(2786.08,3631.89)
  L3-SIG1 w4.05: v1(2786.08,3631.89) 2872.11,3631.89 3029,3475 3029,1750 2947,1668 2947,1587 2915.53,1555.53 2915.53,1049.47 3303,662 3303,185 3320.42,167.58 v1(3320.42,134.86)
SZG_PORTE_S7: J6.22 MC3.142 | length 3689.1
  L3-SIG1 w4.05: v1(2754.08,3651.58) 2881.43,3651.58 3049,3484 3049,1741 2965.5,1657.5 2965.5,1577.5 2956,1568 2956,1466 2941.37,1451.37 2941.37,1056.63 3320.42,677.58 v1(3320.42,360.84)
SZG_PORTE_S8: J6.23 MC3.144 | length 4115.1
  L1-TOP w4.55: MC3.144@2720.08,3671.26 v1(2786.08,3671.26)
  L3-SIG1 w4.05: v1(2786.08,3671.26) 2889.74,3671.26 3069,3492 3069,1736.26 3031,1698.26 3031,1613 2993,1575 2993,1473 2963.51,1443.51 2963.51,1074.49 3359,679 3359,319 3319,279 3319,190 3340.11,168.89 v1(3340.11,32.86)
SZG_PORTE_S9: J6.24 MC3.146 | length 3881.4
  L3-SIG1 w4.05: v1(2754.08,3690.95) 2899.05,3690.95 3097,3493 3097,1739.6 3054.5,1697.1 3054.5,1600.5 3012,1558 3012,1462 2984.04,1434.04 2984.04,1082.96 3374,693 3374,292.73 v1(3340.11,258.84)
SZG_PORTE_TX0N: J6.8 MC2.84 | length 2255.2
  L1-TOP w3.3: J6.8@3103.89,309.84 3103.89,270.48 3098.54,265.13 3098.54,254 3117.54,235 3580,235 3642,297 3642,553.73 4187.27,1099 4215,1099 4512,1396 4512,1425.73 4532.27,1446 4559.16,1446 4571.43,1433.73 4571.43,1422.48 4576.77,1417.13 MC2.84@4576.77,1394.09
SZG_PORTE_TX0P: J6.6 MC2.82 | length 2255.2
  L1-TOP w3.3: J6.6@3084.2,309.84 3084.2,270.91 3089.54,265.57 3089.54,250.27 3113.82,226 3583.73,226 3651,293.27 3651,550 4191,1090 4218.73,1090 4521,1392.27 4521,1422 4536,1437 4555.43,1437 4562.43,1430 4562.43,1422.39 4557.09,1417.05 MC2.82@4557.09,1394.09
SZG_PORTE_TX1N: J6.12 MC2.80 | length 1830.6
  L1-TOP w3.3: J6.12@3162.94,309.84 3162.94,348.97 3157.6,354.32 3157.6,547.87 3850.98,1241.25 4008.75,1241.25 v1(4020,1230) ; MC2.80@4320.87,1394.09 4320.87,1370.91 4315.52,1365.57 4315.52,1347.34 v1(4326.77,1336.09)
  L10-BOT w3.3: v1(4020,1230) 4031.25,1241.25 4266.98,1241.25 4315.52,1289.8 4315.52,1324.85 v1(4326.77,1336.09)
SZG_PORTE_TX1P: J6.10 MC2.78 | length 1830.6
  L1-TOP w3.3: J6.10@3143.26,309.84 3143.26,349.34 3148.6,354.68 3148.6,551.6 3847.25,1250.25 4008.75,1250.25 v1(4020,1261.5) ; v1(4295.28,1336.09) 4306.52,1347.34 4306.52,1365.37 4301.18,1370.71 MC2.78@4301.18,1394.09
  L10-BOT w3.3: v1(4020,1261.5) 4031.25,1250.25 4263.25,1250.25 4306.52,1293.52 4306.52,1324.85 v1(4295.28,1336.09)
SZG_PORTE_TX2N: J6.32 MC2.76 | length 1437.4
  L1-TOP w3.3: J6.32@3458.22,309.84 3458.22,349.17 3452.88,354.51 3452.88,472.15 4090.73,1110 4117.73,1110 4256.47,1248.74 4256.47,1365.8 4261.81,1371.14 MC2.76@4261.81,1394.09
SZG_PORTE_TX2P: J6.30 MC2.74 | length 1437.4
  L1-TOP w3.3: J6.30@3438.53,309.84 3438.53,349.4 3443.88,354.74 3443.88,475.88 4087,1119 4114,1119 4247.47,1252.47 4247.47,1365.74 4242.13,1371.08 MC2.74@4242.13,1394.09
SZG_PORTE_TX3N: J6.28 MC2.72 | length 1453.8
  L1-TOP w3.3: J6.28@3399.16,309.84 3399.16,349.57 3393.82,354.91 3393.82,528.09 4031.73,1166 4086.73,1166 4111.73,1191 4197.41,1276.69 4197.41,1365.35 4202.76,1370.69 MC2.72@4202.76,1394.09
SZG_PORTE_TX3P: J6.26 MC2.70 | length 1452.6
  L1-TOP w3.3: J6.26@3379.48,309.84 3379.48,349 3384.82,354.34 3384.82,451.57 ; 3384.82,452.73 3384.82,531.82 4028,1175 4083,1175 4188.41,1280.41 4188.41,1365.85 4183.07,1371.2 MC2.70@4183.07,1394.09
SZG_PORTF_C2P_CLKN: J7.36 MC1.46 | length 4817.2
  L1-TOP w3.3: MC1.46@3415.35,4268.11 3411.77,4264.53 3411.77,4241.56 3410.01,4239.8 3410.01,4192.39 v1@3419.29,4183.11
  L3-SIG1 w3.15: v1@3419.29,4183.11 3410.01,4173.83 3410.01,4133.99 4359,3185 4359,2640.73 5296,1703.73 5296,1428 5559.17,1164.83 5559.17,1148.55 5559.17,364.12 v1@5568.45,354.84
  other v1: 5569.55,354.84 3420.39,4183.11
SZG_PORTF_C2P_CLKP: J7.34 MC1.44 | length 4817.2
  L1-TOP w3.3: v1@3391.73,4183.11 3401.01,4192.39 3401.01,4240.16 3395.67,4245.5 MC1.44@3395.67,4268.11
  L3-SIG1 w3.15: v1@3391.73,4183.11 3401.01,4173.83 3401.01,4141.27 3401.01,4130.26 4350,3181.27 4350,2637 5287,1700 5287,1441 5287,1424.27 5550.17,1161.1 5550.17,364.12 v1@5540.89,354.84
  other v1: 5539.8,354.84 3390.63,4183.11
SZG_PORTF_P2C_CLKN: J7.35 MC1.36 | length 5291
  L1-TOP w3.3: MC1.36@3316.93,4268.11 3311.59,4262.77 3311.59,4219.41 3392.82,4138.18 3481.62,4138.18 v1(3492,4148.56)
  L3-SIG1 w3.15: v1(3492,4148.56) 3502.38,4138.18 3523.41,4138.18 4411,3250.59 4411,2667.73 5330,1748.73 5330,1440 5607,1163 5607,347 5598,338 5598,124 5593,119 5559.17,85.17 5559.17,48.14 v1@5568.45,38.86
  other v1: 5569.55,38.86
SZG_PORTF_P2C_CLKP: J7.33 MC1.34 | length 5291
  L1-TOP w3.3: MC1.34@3297.24,4268.11 3302.59,4262.77 3302.59,4215.69 3389.09,4129.18 3481.62,4129.18 v1(3492,4118.8)
  L3-SIG1 w3.15: v1(3492,4118.8) 3502.38,4129.18 3519.68,4129.18 4402,3246.86 4402,2664 5321,1745 5321,1436.27 5598,1159.27 5598,350.73 5589,341.73 5589,127.73 5550.17,88.9 5550.17,48.14 v1@5540.9,38.86
  other v1: 5539.8,38.86
SZG_PORTF_REFCLKN: J7.15 MC2.103 | length 2490.3
  L1-TOP w3.3: J7.15@5269.24,83.86 5269.24,123.22 5263.9,128.57 5263.9,149.58 v1@5273.18,158.86
  L10-BOT w3.3: 4866.83,1131.17 4868,1130 5593,405 5593,321 5593,303.05 5590.56,300.6 5584.11,300.6 5581.67,298.16 5581.67,286.75 5584.11,284.3 5590.56,284.3 5593,281.86 5593,225 5593,117.96 5541.78,66.74 5326.16,66.74 5263.9,129 5263.9,149.58 v1@5273.18,158.86 ; 4866.83,1131.17 4863.38,1131.17 4857.26,1125.05 4853.8,1125.05 4845.73,1133.12 4845.73,1136.58 4851.85,1142.69 4851.85,1146.15 4843.78,1154.22 4840.32,1154.22 4834.21,1148.1 4830.75,1148.1 4822.68,1156.17 4822.68,1159.63 4828.8,1165.74 4828.8,1169.2 4822.67,1175.33 4821.5,1176.5 4800.6,1197.4 4800.6,1408.6 4859,1467 4859,1553 4859,1557.55 4900.34,1598.89 4900.34,1624.15 4890.49,1634 4871.7,1634 4866.7,1629 4866.7,1620.65 v1(4877.95,1609.4)
  other v1: 5274.28,158.86
SZG_PORTF_REFCLKP: J7.13 MC2.101 | length 2490.3
  L1-TOP w3.3: v1@5245.62,158.86 5254.9,149.58 5254.9,128.43 5249.56,123.09 J7.13@5249.56,83.86
  L10-BOT w3.3: v1(4846.46,1609.4) 4857.7,1620.65 4857.7,1632.73 4867.98,1643 4887.64,1643 4894.22,1643 4907.12,1630.11 4909.34,1627.88 4909.34,1595.16 4868,1553.82 4868,1463.27 4809.6,1404.87 4809.6,1201.13 5602,408.73 5602,379.59 5602,114.23 5545.51,57.74 5322.43,57.74 5254.9,125.27 5254.9,149.58 v1@5245.62,158.86
  other v1: 5244.52,158.86
SZG_PORTF_RX0N: J7.7 MC2.99 | length 2503.8
  L10-BOT w3.3: v1(4818.9,1665.4) 4807.65,1654.15 4807.65,1574.35 4821,1561 4823.64,1558.36 4823.64,1478.64 4821,1476 4770,1425 4770,1132.73 5506,396.73 5511,391.73 5511,294.73 5547,258.73 5547,177 5536,166 5536,137.73 5542,131.73 5542,111.27 5528.73,98 5436.27,98 5369,165.27 5369,181 5323,227 5138,227 5126,215 5126,177.52 5145.79,157.73 5145.79,138.14 v1@5155.07,128.86
  other v1: 5156.17,128.86
SZG_PORTF_RX0P: J7.5 MC2.97 | length 2503.8
  L10-BOT w3.3: v1(4787.4,1665.4) 4798.65,1654.15 4798.65,1570.62 4814.64,1554.64 4814.64,1482.36 4761,1428.73 4761,1129 5502,388 5502,291 5538,255 5538,180.73 5527,169.73 5527,134 5533,128 5533,115 5525,107 5440,107 5378,169 5378,184.73 5326.73,236 5134.27,236 5117,218.73 5117,173.79 5136.79,154 5136.79,138.14 v1@5127.51,128.86
  other v1: 5126.41,128.86
SZG_PORTF_RX1N: J7.11 MC2.95 | length 2284.6
  L10-BOT w3.3: v1(4759.84,1609.4) 4748.59,1620.65 4748.59,1708.13 4725.73,1731 4642.83,1731 4621.06,1709.23 4621.06,1663.67 4566,1608.61 4566,1605.56 4566,1544 4571,1539 4571,580.27 5047.27,104 5088.27,104 5170.27,22 5197.27,22 v1@5214.12,38.86
  other v1: 5215.22,38.86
